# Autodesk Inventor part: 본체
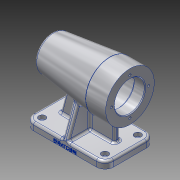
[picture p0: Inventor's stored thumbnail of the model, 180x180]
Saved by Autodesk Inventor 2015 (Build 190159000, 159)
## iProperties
Created: 2018-09
Part Number: 본체
Material: 알루미늄 6061
Document SubType Name: Modeling
Designer: pc
Density: 2.7 g/cm^3
Appearance: 알루미늄 - 평지
Mass: 734.327 g
Surface Area: 664.934 cm^2
Volume: 271.973 cm^3
Author: pc
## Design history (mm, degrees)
sketch "스케치1"
  geometry: L1 (-56, 0)-(56, 0); L2 (-56, 0)-(-56, 34); L3 (-56, 34)-(-28, 34); L4 (-28, 34)-(52.27, 24.144); A1 r 80 centre (-24, 0) between (56, 0) and (52.27, 24.144); 2 further points
  constraints: 8 end point, 2 coincident, 2 point on circle, 1 centre point, 1 horizontal, 1 horizontal alignment, 1 midpoint, 1 perpendicular, 1 vertical
  dimensions: "d1" = 112 distance of L1.start L1.end; "d2" = 28 distance of L2.end L3.end; "d3" = 7 deg angle of L3 L4; "d4" = 80 radius of A1; "d5" = 68 diameter of L3 L1
revolve "회전1" sketch "스케치1" stored, may be unused: angle "d6" = 90 deg
sketch "스케치2"
  geometry: L1 (-56, -34)-(-56, 34) reference; L2 (-56, 0)-(56, 0); L3 (-56, 0)-(-56, 21); L4 (-56, 21)-(-41, 21); L5 (-41, 21)-(-41, 24); L6 (-41, 24)-(13, 24); L7 (13, 24)-(13, 21); L8 (25, 21)-(25, 17.5); L9 (25, 17.5)-(43, 17.5); L10 (43, 17.5)-(43, 16); L11 (43, 16)-(47, 16); L12 (47, 16)-(47, 10.5); L13 (25, 21)-(13, 21); L14 (47, 10.5)-(50, 10.5); L15 (50, 10.5)-(50, 0); A1 r 80 centre (-24, 0) between (52.27, -24.144) and (52.27, 24.144) reference; 1 further point
  constraints: 28 end point, 8 perpendicular, 3 horizontal, 1 midpoint, 1 point on circle, 1 point on line, 1 vertical
  dimensions: "d7" = 42 diameter of L4 L2; "d8" = 15 distance of L3.end L4.end; "d9" = 48 diameter of L6 L2; "d10" = 54 distance between parallel lines of L7 L5; "d11" = 12 distance of L8.start L7.end; "d12" = 42 diameter of L13 L2; "d13" = 18 distance between parallel lines of L10 L8; "d14" = 35 diameter of L9 L2; "d15" = 32 diameter of L11 L2; "d16" = 4 distance between parallel lines of L12 L10; "d17" = 21 diameter of L14 L2; "d18" = 3 distance between parallel lines of L12 L15
revolve "회전2" sketch "스케치2" stored, may be unused: angle "d19" = 90 deg
fillet "모깎기1" dims "d24" = 3, "d25" = 0.3
node "작업 평면1"
sketch "스케치3"
  geometry: L1 (-56, -35)-(56, -35); L2 (56, -35)-(56, 35); L3 (56, 35)-(-56, 35); L4 (-56, 35)-(-56, -35); L5 (-56, -35)-(56, 35); L6 (56, -35)-(-56, 35); 1 further point
  constraints: 12 end point, 2 midpoint, 2 parallel, 1 horizontal, 1 perpendicular
  dimensions: "d31" = 112 distance of L3.end L2.end; "d32" = 70 distance of L2.end L1.end
extrude "돌출1" join sketch "스케치3" distance "d33" = 10; taper "d34" = 0 deg
sketch "스케치8"
  geometry: L1 (38, 4)-(-38, 4); L2 (-38, 4)-(-38, -4); L3 (-38, -4)-(38, -4); L4 (38, -4)-(38, 4); L5 (38, 4)-(-38, -4); L6 (-38, 4)-(38, -4); L7 (56, -35)-(56, 35) reference; L8 (-56, 35)-(-56, -35) reference; 1 further point
  constraints: 12 end point, 2 midpoint, 2 parallel, 1 horizontal, 1 perpendicular
  dimensions: "d61" = 8 distance of L2.end L1.end; "d62" = 18 distance between parallel lines of L7 L4; "d63" = 18 distance between parallel lines of L8 L2 (derived)
extrude "돌출4" join sketch "스케치8" stored distance "d64" = 10; taper "d65" = 0 deg
sketch "스케치9"
  geometry: L1 (-18, -10)-(-18, 0) reference; L2 (-9, 79.182)-(-9, 73.708) reference; L3 (-12, 70.344)-(-12, 57.656) reference; L4 (-9, 54.292)-(-9, 48.818) reference; L5 (-8.7, 48.508)-(-5, 48.508) reference; L6 (-5, 48.508)-(-5, 47.272) reference; L7 (-4.7, 46.963)-(13, 46.963) reference; L8 (13, 46.963)-(13, 43.69) reference; L9 (13.3, 43.384)-(25, 43.384) reference; L10 (28, 40.336)-(76, 40.336) reference; L11 (79, 43.384)-(94, 43.384) reference; L12 (94, 43.384)-(94, 30.236) reference; L13 (94, 30.236)-(76, 30.236) reference; L14 (76, 30.236)-(76, 0) reference; L15 (0, 0)-(76, 0) reference; L16 (-18, 0)-(0, 0) reference; L17 (-18, -10)-(-18, 0) reference; L18 (94, -10)-(-18, -10) reference; L19 (94, 0)-(94, -10) reference; L20 (76, 0)-(94, 0) reference; L21 (-5, 79.492)-(-8.7, 79.492) reference; L22 (-5, 80.728)-(-5, 79.492) reference; L23 (13, 81.037)-(-4.7, 81.037) reference; L24 (13, 84.31)-(13, 81.037) reference; L25 (25, 84.616)-(13.3, 84.616) reference; L26 (76, 87.664)-(28, 87.664) reference; L27 (94, 84.616)-(79, 84.616) reference; L28 (94, 97.764)-(94, 84.616) reference; L29 (66, 97.764)-(94, 97.764) reference; L30 (0, 0)-(0, 38.415) reference; L31 (76, 30.236)-(66, 30.236) reference; L32 (0, 0)-(9.962, 37.177); L33 (0, 0)-(0, 38.415); L34 (94, 0)-(-18, 0) reference; L35 (0, 38.415)-(9.962, 37.177); A1 r 79.9 centre (62, 64) between (-14.27, 87.81) and (-14.27, 40.19) reference; 1 further point
  constraints: 6 end point, 1 perpendicular, 16 other
  dimensions: "d66" = 105 deg angle of L16 L32; "d67" = 18 distance from line of L1 L15.start (derived)
extrude "돌출5" cut sketch "스케치9" stored distance "d68" = 10; taper "d69" = 0 deg
sketch "스케치10"
  geometry: L1 (-64, -35)-(-74, -35) reference; L2 (-74, -35)-(-74, 35) reference; L3 (-74, 35)-(-64, 35) reference; L4 (-64, 35)-(-64, 4) reference; L5 (-64, 4)-(-30.299, 4) reference; L6 (-30.299, -4)-(-64, -4) reference; L7 (-64, -4)-(-64, -35) reference; L8 (-64, -35)-(-23.032, -20.089); L9 (-64, 35)-(-23.032, 20.089); C1 r 24 at (0, 0) reference; A1 r 30.562 centre (0, 0) between (-30.299, -4) and (-30.299, 4) reference; 1 further point
  constraints: 4 end point, 2 point on circle
  dimensions: "d70" = 20 deg angle of L1 L8; "d71" = 20 deg angle of L3 L9
  node "절단 모서리 투영4"
feature "리브3" dims "d72" = 1, "d73" = 8, "d74" = 0, "d75" = 0, "d76" = 1, "d77" = 1
feature "리브4" dims "d78" = 1, "d79" = 8, "d80" = 0, "d81" = 0, "d82" = 1, "d83" = 1
sketch "스케치11"
  geometry: 2 further points
  constraints: 1 vertical alignment
  dimensions: "d84" = 26 distance of point (0, 0) point (0, 26)
hole "구멍1" sketch "스케치11" at (0, 26) diameter "d85" = 3.242; stored, may be unused: countersink angle "d89" = 90 deg, drill point angle "d91" = 118 deg; dims "d86" = 8, "d87" = 4, "d88" = 2, "d90" = 11
chamfer "모따기1" distance "d95" = 1; stored, may be unused: second distance "d96" = 2, angle "d97" = 45 deg
fillet "모깎기2" dims "d106" = 12
sketch "스케치12"
  geometry: A1 r 12 centre (44, -23) between (44, -35) and (56, -23) reference; A2 r 12 centre (44, 23) between (56, 23) and (44, 35) reference; A3 r 12 centre (-44, 23) between (-44, 35) and (-56, 23) reference; A4 r 12 centre (-44, -23) between (-56, -23) and (-44, -35) reference; 1 further point
hole "구멍2" sketch "스케치12" at (44, -23), (44, 23), (-44, 23), (-44, -23) diameter "d107" = 5.5; stored, may be unused: countersink angle "d111" = 90 deg, drill point angle "d113" = 0 deg; dims "d108" = 8, "d109" = 9.5, "d110" = 5.4, "d112" = 10
fillet "모깎기4" dims "d116" = 3
fillet "모깎기5" dims "d117" = 3
fillet "모깎기6" dims "d118" = 3
sketch "스케치13"
  geometry: L1 (100, 0)-(100, 7) reference; L2 (100, 0)-(88, 0) reference; 2 further points
  constraints: 1 other
  dimensions: "d119" = 56 distance from line of L1 point (44, 3); "d120" = 3 distance from line of L2 point (44, 3)
feature "엠보싱1" sketch "스케치13" dims "d7" = 42, "d121" = 0.5, "d122" = 0
node "솔리드1"
pattern_circular "원형 패턴1" dims angle "d93" = 360 deg
node "절단 모서리 투영3"
other parameters: "d20" = 0.5, "d21" = 2, "d22" = 0, "d26" = 0.5, "d27" = 2, "d28" = -75, "d30" = -74, "d43" = 105 deg, "d98" = 0.5, "d99" = 2, "d100" = 0, "d102" = 0.5, "d103" = 2, "d104" = 130.5
